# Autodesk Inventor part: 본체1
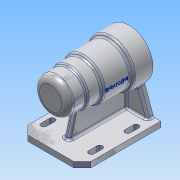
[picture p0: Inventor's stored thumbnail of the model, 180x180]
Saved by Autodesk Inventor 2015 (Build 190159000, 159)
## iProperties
Created: 2017-09
Part Number: 본체1
Material: 알루미늄 6061
Document SubType Name: Modeling
Designer: 김선찬
Density: 2.7 g/cm^3
Appearance: 알루미늄 - 평지
Mass: 693.606 g
Surface Area: 708.752 cm^2
Volume: 256.891 cm^3
Author: 김선찬
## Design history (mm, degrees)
sketch "스케치1"
  geometry: L1 (-56, 8)-(56, 8); L2 (56, 8)-(56, 0); L3 (56, 0)-(-56, 0); L4 (-56, 0)-(-56, 8); L5 (-56, 70)-(56, 70); L6 (-56, 70)-(-56, 95); L7 (-56, 95)-(-31, 95); L8 (-31, 95)-(-31, 97); L9 (-31, 97)-(-11, 97); L10 (-11, 97)-(-11, 100); L11 (-11, 100)-(28, 100); L12 (28, 100)-(28, 104); L13 (28, 104)-(56, 104); L14 (56, 104)-(56, 70); L15 (-50, 70)-(-50, 80.5); L16 (-50, 80.5)-(-47, 80.5); L17 (-47, 80.5)-(-47, 86); L18 (-47, 86)-(-43, 86); L19 (-43, 86)-(-43, 87.5); L20 (-43, 87.5)-(-25, 87.5); L21 (-25, 87.5)-(-25, 91); L22 (-25, 91)-(-13, 91); L23 (-13, 91)-(-13, 94); L24 (-13, 94)-(41, 94); L25 (41, 94)-(41, 91); L26 (41, 91)-(56, 91); L27 (-22.81, 49.76)-(-34, 8); L28 (56, 8)-(56, 49.76); L29 (-22.81, 49.76)-(56, 49.76); 3 further points
  constraints: 58 end point, 20 perpendicular, 4 horizontal, 3 point on line, 2 midpoint, 2 parallel, 2 vertical, 1 coincident, 1 vertical alignment
  dimensions: "d0" = 70 distance from line of point (0, 0) L5; "d1" = 112 distance of L2.end L3.end; "d2" = 112 distance of L5.start L5.end; "d3" = 50 diameter of L7 L5; "d4" = 54 diameter of L9 L5; "d5" = 60 diameter of L11 L5; "d6" = 68 diameter of L13 L5; "d7" = 42 diameter of L26 L5; "d8" = 48 diameter of L24 L5; "d9" = 42 diameter of L22 L5; "d10" = 35 diameter of L20 L5; "d11" = 32 diameter of L18 L5; "d12" = 21 diameter of L16 L5; "d13" = 84 distance between parallel lines of L12 L6; "d14" = 45 distance between parallel lines of L6 L10; "d15" = 25 distance between parallel lines of L6 L8; "d16" = 3 distance between parallel lines of L17 L15; "d17" = 4 distance between parallel lines of L19 L17; "d18" = 18 distance between parallel lines of L21 L19; "d19" = 12 distance between parallel lines of L23 L21; "d20" = 54 distance between parallel lines of L25 L23; "d21" = 15 distance between parallel lines of L14 L25; "d22" = 8 distance between parallel lines of L3 L1; "d23" = 105 deg angle of L1 L27; "d24" = 22 distance from line of L4 L27.end; "d33" = 49.76015 distance between parallel lines of L3 L29
extrude "돌출1" new body sketch "스케치1" stored distance "d25" = 90; taper "d26" = 0 deg
revolve "회전1" stored, may be unused: angle "d27" = 90 deg
fillet "모깎기1" dims "d28" = 3
fillet "모깎기2" dims "d29" = 9
extrude "돌출2" join sketch "스케치1" stored distance "d30" = 8; taper "d31" = 0 deg
revolve "회전2" stored, may be unused: angle "d32" = 90 deg
sketch "스케치2"
  geometry: L1 (66.9, -43.992)-(80, -8); L2 (90, -8)-(49, -8) reference; L3 (90, 0)-(90, -8) reference; A1 r 34 centre (45, -70) between (41, -36.236) and (49, -36.236) reference; 1 further point
  constraints: 2 end point, 1 point on circle, 1 point on line
  dimensions: "d34" = 10 distance from line of L1.end L3; "d35" = 110 deg angle of L2 L1
feature "리브1" sketch "스케치2" dims "d36" = 1, "d37" = 8, "d38" = 0, "d39" = 0, "d40" = 1, "d41" = 1
chamfer "모따기1" distance "d42" = 12; stored, may be unused: second distance "d43" = 2, angle "d44" = 45 deg
sketch "스케치3"
  geometry: L1 (-43.992, 56)-(-104, 56) reference; L2 (0, -44)-(0, 56) reference; 3 further points
  constraints: 1 midpoint, 1 other
  dimensions: "d45" = 48 distance from line of L1 point (-70, 8); "d88" = 70 distance from line of L2 point (-70, 8)
feature "엠보싱1" sketch "스케치3" dims "d0" = 70, "d1" = 112, "d2" = 112, "d3" = 50, "d4" = 54, "d5" = 60, "d6" = 68, "d7" = 42, "d8" = 48, "d9" = 42, "d10" = 35, "d11" = 32, "d12" = 21, "d13" = 84, "d14" = 45, "d15" = 25, "d16" = 3, "d17" = 4, "d18" = 18, "d19" = 12, "d20" = 54, "d21" = 15, "d22" = 8, "d23" = 105 deg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
fillet "모깎기3" dims "d48" = 3
fillet "모깎기4" dims "d49" = 0.3
fillet "모깎기5" dims "d50" = 3
chamfer "모따기2" distance "d51" = 1; stored, may be unused: second distance "d52" = 2, angle "d53" = 45 deg
sketch "스케치4"
  geometry: L1 (-30, 54)-(-30, 66); L2 (-26, 54)-(-26, 66); L3 (-34, 66)-(-34, 54); L4 (49, 90)-(-41, 90) reference; L5 (-30, 54)-(-30, 14); L6 (-30, 14)-(-30, 2); L7 (-34, 14)-(-34, 2); L8 (-26, 2)-(-26, 14); A1 r 4 centre (-30, 54) between (-34, 54) and (-26, 54); A2 r 4 centre (-30, 66) between (-26, 66) and (-34, 66); A3 r 4 centre (-30, 14) between (-26, 14) and (-34, 14); A4 r 4 centre (-30, 2) between (-34, 2) and (-26, 2); 3 further points
  constraints: 18 end point, 8 point on circle, 8 tangent, 4 centre point, 2 midpoint, 2 parallel, 2 vertical, 1 point on line
  dimensions: "d54" = 12 distance of L1.start L1.end; "d56" = 4 radius of A2; "d57" = 34 horizontal distance of point (-30, 60) point (4, 34); "d59" = 24 distance from line of L1.end L4; "d68" = 40 distance of L1.start L5.end; "d69" = 12 distance of L5.end L6.end; "d70" = 8 diameter of A4
extrude "돌출3" cut sketch "스케치4" distance "d60" = 8; taper "d61" = 0 deg
sketch "스케치5"
  geometry: C1 r 22 at (45, -70) reference; 2 further points
  constraints: 1 vertical alignment
  dimensions: "d74" = 26 distance of C1.centre point (45, -96)
hole "구멍1" sketch "스케치5" at (45, -96) diameter "d75" = 3.242; stored, may be unused: countersink angle "d79" = 90 deg, drill point angle "d81" = 118 deg; dims "d76" = 8, "d77" = 4, "d78" = 2, "d80" = 11
fillet "모깎기6" dims "d85" = 3
fillet "모깎기7" dims "d86" = 3
fillet "모깎기8" dims "d87" = 3
node "솔리드1"
mirror "대칭1"
pattern_linear "직사각형 패턴1" dims "d64" = 68
pattern_linear "직사각형 패턴2" dims "d67" = 48
pattern_linear "직사각형 패턴3" dims "d73" = 68
pattern_circular "원형 패턴1" dims angle "d83" = 360 deg
